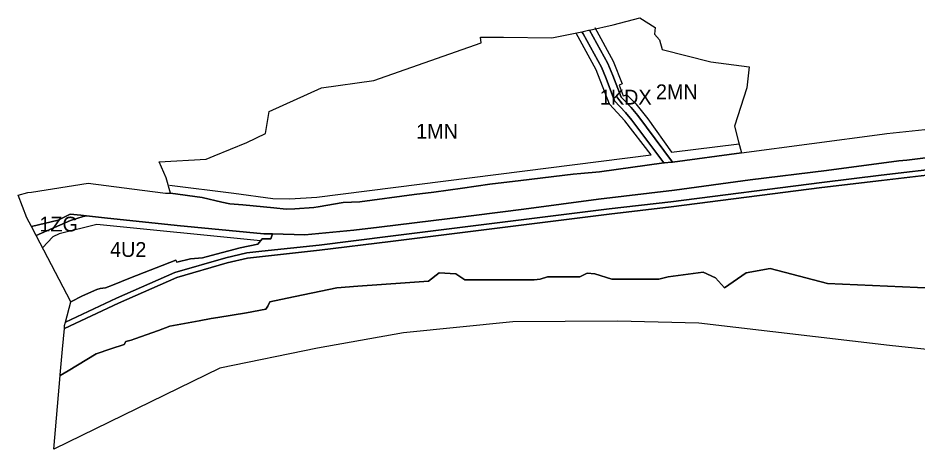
# Model space of a CAD drawing. Extents: x -300162 to -296646, y 29434 to 30761.
# Drawn here: x -300162 to -299553, y 30077 to 30368 of the extents above; entities that cross this region are included whole.
import ezdxf

# ---------------------------------------------------------------- set-up
doc = ezdxf.new("R2010")
doc.units = 0
for name, color, linetype in [('linie_rozgraniczajace', 7, 'Continuous'), ('linie_zabudowy_nieprzekraczalne', 7, 'Continuous'), ('oznaczenia_przeznaczen', 7, 'Continuous')]:
    doc.layers.add(name, color=color, linetype=linetype)

msp = doc.modelspace()

# ---------------------------------------------------------------- linework, layer by layer
at = {"layer": 'linie_rozgraniczajace'}
for points in [[(-299775.404, 30360.192), (-299759.35, 30363.81), (-299741.42, 30368.38), (-299731.08, 30362.05), (-299731.48, 30357.35), (-299728.23, 30353.66), (-299726.34, 30347.1), (-299693.43, 30338.74), (-299667.43, 30335.36), (-299669.03, 30321.27), (-299677.36, 30295.23), (-299674.7, 30284.69), (-299672.74, 30277.3), (-299719.245, 30270.933), (-299742.858, 30302.519), (-299747.191, 30307.781), (-299754.1, 30314.89), (-299759.58, 30329.51), (-299763.005, 30337.524), (-299775.334, 30360.063)], [(-300066.1, 30271.21), (-300034.36, 30273.05), (-300029.13, 30275.18), (-300006.95, 30284.22), (-299994.4, 30290.23), (-299991.8, 30305.08), (-299956.603, 30321.155), (-299921.04, 30326.02), (-299848.51, 30351.61), (-299849.07, 30355.53), (-299833.56, 30355.44), (-299800.96, 30354.96), (-299780.525, 30359.134), (-299779.72, 30357.664), (-299767.392, 30335.124), (-299764.144, 30327.44), (-299758.46, 30312.277), (-299751.051, 30304.603), (-299746.792, 30299.431), (-299725.11, 30270.428), (-299768.64, 30264.4), (-299781.25, 30263.3), (-299786.51, 30262.76), (-299821.77, 30258.47), (-299842.68, 30256.04), (-299861.26, 30253.37), (-299880.54, 30250.6), (-299893.95, 30249.01), (-299930.55, 30244.14), (-299941.89, 30243.72), (-299958.79, 30240.69), (-299961.72, 30240.32), (-299974.51, 30239.29), (-299980.31, 30239.14), (-299988.65, 30240.01), (-300009.71, 30242.07), (-300018.47, 30242.72), (-300023.74, 30243.91), (-300037.15, 30246.95), (-300058.52, 30249.88), (-300061.38, 30260.28)], [(-299780.525, 30359.134), (-299775.99, 30360.06), (-299775.404, 30360.192), (-299775.334, 30360.063), (-299763.005, 30337.524), (-299759.58, 30329.51), (-299754.1, 30314.89), (-299747.191, 30307.781), (-299742.858, 30302.519), (-299719.245, 30270.933), (-299720, 30270.83), (-299724.81, 30270.47), (-299725.11, 30270.428), (-299746.792, 30299.431), (-299751.051, 30304.603), (-299758.46, 30312.277), (-299764.144, 30327.44), (-299767.392, 30335.124), (-299779.72, 30357.664)], [(-300152.49, 30227.42), (-300134.35, 30231.75), (-300126.32, 30235.73), (-300119.03, 30235.09), (-300115.316, 30234.678), (-300117.63, 30234.312), (-300126.127, 30231.6), (-300149.349, 30221.385)], [(-300149.349, 30221.385), (-300126.127, 30231.6), (-300117.63, 30234.312), (-300115.316, 30234.678), (-300103.08, 30233.32), (-300054.06, 30228.21), (-299995.47, 30222.54), (-299989.58, 30222.39), (-299990.684, 30219.156), (-299996.491, 30219.156), (-299999.593, 30215.395), (-300011.399, 30212.972), (-300031.134, 30207.874), (-300036.929, 30206.242), (-300045.1, 30205.6), (-300054.2, 30203.3), (-300055, 30204.8), (-300085.48, 30192.65), (-300097.71, 30187.81), (-300102.39, 30186.1), (-300106.06, 30185.52), (-300108.41, 30184.77), (-300117.98, 30180.56), (-300125.97, 30176.46)]]:
    msp.add_lwpolyline(points, close=True, dxfattribs=at)
for points in [[(-298411.983, 30321.944), (-298435.322, 30325.072), (-298459.41, 30326.755), (-298515.201, 30326.234), (-298602.527, 30322.423), (-298644.17, 30321.06), (-298847.863, 30312.434), (-298932.801, 30309.229), (-299050.017, 30304.032), (-299100.2, 30301.807), (-299188.598, 30298.778), (-299229.999, 30296.988), (-299291.165, 30294.343), (-299340.632, 30290.463), (-299399.471, 30283.938), (-299463.795, 30275.739), (-299532.22, 30267.554), (-299578.276, 30262.044)], [(-300161.58, 30248.61), (-300154.86, 30250.36), (-300152.55, 30250.63), (-300114.19, 30256.68), (-300077.74, 30252.03), (-300061.93, 30250), (-300058.52, 30249.88), (-300037.15, 30246.95), (-300023.74, 30243.91), (-300018.47, 30242.72), (-300009.71, 30242.07), (-299988.65, 30240.01), (-299980.31, 30239.14), (-299974.51, 30239.29), (-299961.72, 30240.32), (-299958.79, 30240.69), (-299941.89, 30243.72), (-299930.55, 30244.14), (-299893.95, 30249.01), (-299880.54, 30250.6), (-299861.26, 30253.37), (-299842.68, 30256.04), (-299821.77, 30258.47), (-299786.51, 30262.76), (-299781.25, 30263.3), (-299768.64, 30264.4), (-299725.11, 30270.428), (-299724.81, 30270.47), (-299720, 30270.83), (-299719.245, 30270.933), (-299672.74, 30277.3), (-299577.57, 30289.96), (-299574.46, 30290.36), (-299548.94, 30293.08)], [(-300129.521, 30162.739), (-300125.97, 30176.46), (-300117.98, 30180.56), (-300108.41, 30184.77), (-300106.06, 30185.52), (-300102.39, 30186.1), (-300097.71, 30187.81), (-300085.48, 30192.65), (-300055, 30204.8), (-300054.2, 30203.3), (-300045.1, 30205.6), (-300036.929, 30206.242), (-300031.134, 30207.874), (-300011.399, 30212.972), (-299999.593, 30215.395), (-299996.491, 30219.156), (-299990.684, 30219.156), (-299989.58, 30222.39), (-299967.71, 30221.83), (-299934.69, 30224.97), (-299917.58, 30227.01), (-299869.89, 30232.88), (-299853.61, 30234.92), (-299819.73, 30239.15), (-299769.4, 30245.91), (-299718.05, 30252.06), (-299666.78, 30258.88), (-299615.17, 30265.21), (-299566.4, 30271.9), (-299560.99, 30272.22), (-299510.09, 30278.52)], [(-299510.09, 30278.52), (-299560.99, 30272.22), (-299566.4, 30271.9), (-299615.17, 30265.21), (-299666.78, 30258.88), (-299718.05, 30252.06), (-299769.4, 30245.91), (-299819.73, 30239.15), (-299853.61, 30234.92), (-299869.89, 30232.88), (-299917.58, 30227.01), (-299934.69, 30224.97), (-299967.71, 30221.83), (-299989.58, 30222.39), (-299995.47, 30222.54), (-300054.06, 30228.21), (-300103.08, 30233.32), (-300115.316, 30234.678)], [(-300130.267, 30158.525), (-300130.09, 30160.54), (-300129.521, 30162.739), (-300095.01, 30178.909), (-300055.507, 30196.286), (-300021.167, 30206.321), (-300006.984, 30209.605), (-299996.832, 30210.698), (-299958.076, 30214.863), (-299909.945, 30220.869), (-299762.234, 30239.304), (-299720.386, 30244.168), (-299618.466, 30257.237), (-299578.276, 30262.044), (-299532.22, 30267.554)], [(-300133.048, 30126.789), (-300133.02, 30127.11), (-300132.15, 30137.01), (-300131.5, 30144.47), (-300130.267, 30158.525), (-300093.563, 30175.722), (-300054.306, 30192.99), (-300020.28, 30202.933), (-300006.4, 30206.148), (-299996.458, 30207.218), (-299957.962, 30211.365), (-299909.831, 30217.371), (-299762.12, 30235.805), (-299720.271, 30240.67), (-299618.351, 30253.739), (-299578.161, 30258.546), (-299532.105, 30264.056)], [(-299532.105, 30264.056), (-299578.161, 30258.546), (-299618.351, 30253.739), (-299720.271, 30240.67), (-299762.12, 30235.805), (-299909.831, 30217.371), (-299957.962, 30211.365), (-299996.458, 30207.218), (-300006.4, 30206.148), (-300020.28, 30202.933), (-300054.306, 30192.99), (-300093.563, 30175.722), (-300130.267, 30158.525)], [(-299578.276, 30262.044), (-299618.466, 30257.237), (-299720.386, 30244.168), (-299762.234, 30239.304), (-299909.945, 30220.869), (-299958.076, 30214.863), (-299996.832, 30210.698), (-300006.984, 30209.605), (-300021.167, 30206.321), (-300055.507, 30196.286), (-300095.01, 30178.909), (-300129.521, 30162.739)], [(-300115.316, 30234.678), (-300119.03, 30235.09), (-300126.32, 30235.73), (-300134.35, 30231.75), (-300152.49, 30227.42), (-300155.6, 30233.4), (-300161.58, 30248.61)], [(-300137.4, 30077.05), (-300133.048, 30126.789), (-300127.71, 30130), (-300108.868, 30141.335), (-300098.864, 30144.714), (-300089.738, 30147.797), (-300088.735, 30149.677), (-300085.163, 30150.588), (-300082.647, 30151.532), (-300066.688, 30157.216), (-300059.013, 30159.971), (-300039.252, 30163.641), (-300031.049, 30165.164), (-300026.508, 30166.007), (-300007.267, 30169.124), (-299994.23, 30171.518), (-299992.864, 30173.621), (-299991.397, 30176.598), (-299979.817, 30179.01), (-299946.17, 30186.02), (-299932.04, 30187.036), (-299899.976, 30189.343), (-299884.254, 30190.584), (-299876.955, 30196.08), (-299865.798, 30195.343), (-299859.73, 30191.388), (-299812.874, 30191.427), (-299808.784, 30191.757), (-299803.908, 30193.385), (-299781.973, 30193.434), (-299777.001, 30195.847), (-299771.863, 30195.401), (-299760.29, 30191.776), (-299728.642, 30191.863), (-299722.332, 30193.414), (-299698.507, 30196.477), (-299690.316, 30192.852), (-299684.161, 30186.086), (-299669.661, 30196.186), (-299653.376, 30199.094), (-299614.566, 30188.897), (-299523.393, 30184.807)], [(-299523.393, 30184.807), (-299614.566, 30188.897), (-299653.376, 30199.094), (-299669.661, 30196.186), (-299684.161, 30186.086), (-299690.316, 30192.852), (-299698.507, 30196.477), (-299722.332, 30193.414), (-299728.642, 30191.863), (-299760.29, 30191.776), (-299771.863, 30195.401), (-299777.001, 30195.847), (-299781.973, 30193.434), (-299803.908, 30193.385), (-299808.784, 30191.757), (-299812.874, 30191.427), (-299859.73, 30191.388), (-299865.798, 30195.343), (-299876.955, 30196.08), (-299884.254, 30190.584), (-299899.976, 30189.343), (-299932.04, 30187.036), (-299946.17, 30186.02), (-299979.817, 30179.01), (-299991.397, 30176.598), (-299992.864, 30173.621), (-299994.23, 30171.518), (-300007.267, 30169.124), (-300026.508, 30166.007), (-300031.049, 30165.164), (-300039.252, 30163.641), (-300059.013, 30159.971), (-300066.688, 30157.216), (-300082.647, 30151.532), (-300085.163, 30150.588), (-300088.735, 30149.677), (-300089.738, 30147.797), (-300098.864, 30144.714), (-300108.868, 30141.335), (-300127.71, 30130), (-300133.048, 30126.789)], [(-299150.7, 30127.43), (-299298.12, 30135.89), (-299475.25, 30140.46), (-299520, 30141.4), (-299572.63, 30146.97), (-299701.49, 30162.19), (-299756.58, 30163.55), (-299827.31, 30163.1), (-299901.06, 30155.64), (-299959.13, 30145.19), (-300025.15, 30131.74), (-300137.4, 30077.05)]]:
    msp.add_lwpolyline(points, dxfattribs=at)
at = {"layer": 'linie_zabudowy_nieprzekraczalne'}
for points in [[(-299751.603, 30298.778), (-299761.917, 30310.134), (-299771.024, 30333.429), (-299784.537, 30358.134)], [(-299771.824, 30361.983), (-299759.375, 30339.222), (-299753.36, 30323.934)], [(-299753.36, 30323.934), (-299755.308, 30323.086)], [(-299755.308, 30323.086), (-299752.572, 30315.681)], [(-299752.572, 30315.681), (-299750.119, 30316.533)], [(-299750.132, 30316.546), (-299744.186, 30310.428), (-299736.084, 30300.263)], [(-299733.665, 30275.896), (-299751.603, 30298.778)], [(-299736.084, 30300.263), (-299719.93, 30277.602)], [(-299719.93, 30277.602), (-299674.379, 30283.418)], [(-300059.224, 30255.287), (-300015.853, 30249.9), (-299989.438, 30246.309), (-299977.98, 30246.142), (-299959.587, 30247.231), (-299733.665, 30275.896)], [(-299997.663, 30217.735), (-300108.344, 30228.823), (-300133.749, 30222.402), (-300137.937, 30220.392), (-300144.964, 30212.958)]]:
    msp.add_lwpolyline(points, dxfattribs=at)

# ---------------------------------------------------------------- texts
at = {"layer": 'oznaczenia_przeznaczen'}
for s, p in [('2MN', (-299730.517041, 30313.490001)), ('1KDX', (-299768.382557, 30309.890001)), ('1MN', (-299892.557016, 30286.840001)), ('1ZG', (-300147.126278, 30224.070001)), ('4U2', (-300099.373717, 30206.890001))]:
    msp.add_text(s, height=10, dxfattribs=at).set_placement(p)

doc.saveas('drawing.dxf')
